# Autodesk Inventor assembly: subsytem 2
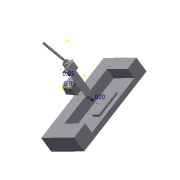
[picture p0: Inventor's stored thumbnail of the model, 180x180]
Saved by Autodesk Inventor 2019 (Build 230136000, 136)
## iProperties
Created: 2020-04
Part Number: subsytem 2
Document SubType Name: Assembly
Designer: Krupashree
Author: Krupashree
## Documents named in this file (4)
- A:\sec sem notes\Engg explorRION\MODELLING\subsytem 2.iam
- A:\sec sem notes\Engg explorRION\MODELLING\motor.ipt
- A:\sec sem notes\Engg explorRION\MODELLING\body final.ipt
- A:\sec sem notes\Engg explorRION\MODELLING\pen to holder.iam
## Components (3 placed, 3 different names)
1. body final:1 — Mate:1
2. motor:1 — Mate:1, Mate:2
3. pen to holder:1 [sub-assembly] — Flush:1, Mate:2
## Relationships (3: Mate 2, Flush 1)
- Mate:1: body final:1 ↔ motor:1
- Flush:1: pen to holder:1
- Mate:2: motor:1 ↔ pen to holder:1
